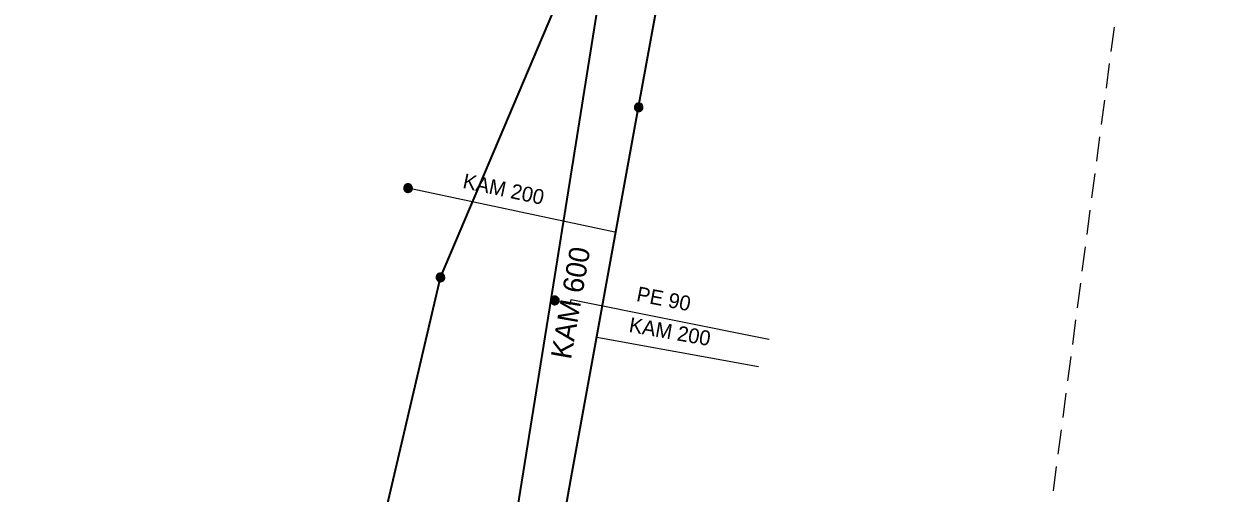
# Model space of a CAD drawing. Extents: x -867121 to -866743, y -1014362 to -1014088.
# Drawn here: x -866806.4 to -866742.8, y -1014182.3 to -1014157.2 of the extents above; entities that cross this region are included whole.
import ezdxf

# ---------------------------------------------------------------- set-up
doc = ezdxf.new("R2010")
doc.units = 0
doc.header["$LTSCALE"] = 0.44
doc.linetypes.add('MEDIUM_DASHED', pattern=[4.5, 3, -1.5])
for name, color, linetype, lineweight in [('1', 7, 'Continuous', 35), ('12', 7, 'Continuous', 13), ('21', 7, 'Continuous', 35), ('23', 7, 'Continuous', 25), ('3', 7, 'Continuous', 25), ('32', 7, 'Continuous', 13), ('62', 7, 'MEDIUM_DASHED', 25)]:
    doc.layers.add(name, color=color, linetype=linetype, lineweight=lineweight)

msp = doc.modelspace()

# ---------------------------------------------------------------- linework, layer by layer
at = {"layer": '1'}
msp.add_lwpolyline([(-866791.979, -1014256.58), (-866792.57, -1014256.02), (-866792.709, -1014255.69), (-866792.69, -1014255.37), (-866792.5, -1014254.9), (-866792.3, -1014254.24), (-866792, -1014252.89), (-866783.03, -1014202.67), (-866778.1, -1014171.95), (-866772.02, -1014133.72), (-866768.851, -1014115.7)], dxfattribs=at)
at = {"layer": '12'}
for points in [[(-866777.676, -1014172.009), (-866777.682, -1014171.957), (-866777.699, -1014171.907), (-866777.728, -1014171.863), (-866777.765, -1014171.826), (-866777.81, -1014171.799), (-866777.86, -1014171.782), (-866777.913, -1014171.778), (-866777.965, -1014171.785), (-866778.014, -1014171.804), (-866778.057, -1014171.833), (-866778.093, -1014171.872), (-866778.119, -1014171.917), (-866778.135, -1014171.968), (-866778.138, -1014172.02), (-866778.13, -1014172.072), (-866778.11, -1014172.121), (-866778.079, -1014172.164), (-866778.04, -1014172.198), (-866777.994, -1014172.224), (-866777.943, -1014172.238), (-866777.89, -1014172.24), (-866777.839, -1014172.23), (-866777.791, -1014172.209), (-866777.748, -1014172.178), (-866777.714, -1014172.137), (-866777.69, -1014172.091), (-866777.678, -1014172.04)], [(-866777.706, -1014172.009), (-866777.712, -1014171.96), (-866777.729, -1014171.914), (-866777.757, -1014171.874), (-866777.794, -1014171.842), (-866777.838, -1014171.82), (-866777.886, -1014171.809), (-866777.935, -1014171.809), (-866777.982, -1014171.822), (-866778.025, -1014171.846), (-866778.061, -1014171.879), (-866778.088, -1014171.92), (-866778.104, -1014171.967), (-866778.108, -1014172.016), (-866778.101, -1014172.064), (-866778.082, -1014172.109), (-866778.052, -1014172.149), (-866778.014, -1014172.18), (-866777.97, -1014172.2), (-866777.922, -1014172.21), (-866777.873, -1014172.208), (-866777.826, -1014172.193), (-866777.783, -1014172.168), (-866777.749, -1014172.134), (-866777.723, -1014172.092), (-866777.709, -1014172.045)], [(-866777.736, -1014172.009), (-866777.742, -1014171.964), (-866777.759, -1014171.922), (-866777.787, -1014171.887), (-866777.823, -1014171.86), (-866777.865, -1014171.843), (-866777.91, -1014171.838), (-866777.955, -1014171.844), (-866777.996, -1014171.863), (-866778.031, -1014171.891), (-866778.058, -1014171.928), (-866778.074, -1014171.97), (-866778.078, -1014172.015), (-866778.071, -1014172.06), (-866778.052, -1014172.101), (-866778.023, -1014172.135), (-866777.986, -1014172.161), (-866777.943, -1014172.177), (-866777.898, -1014172.18), (-866777.853, -1014172.172), (-866777.813, -1014172.152), (-866777.779, -1014172.123), (-866777.753, -1014172.085), (-866777.739, -1014172.042)], [(-866777.766, -1014172.009), (-866777.771, -1014171.968), (-866777.789, -1014171.931), (-866777.816, -1014171.9), (-866777.851, -1014171.879), (-866777.891, -1014171.868), (-866777.932, -1014171.87), (-866777.971, -1014171.883), (-866778.005, -1014171.907), (-866778.03, -1014171.939), (-866778.045, -1014171.977), (-866778.048, -1014172.018), (-866778.04, -1014172.058), (-866778.02, -1014172.094), (-866777.991, -1014172.123), (-866777.954, -1014172.142), (-866777.914, -1014172.15), (-866777.873, -1014172.146), (-866777.835, -1014172.131), (-866777.803, -1014172.105), (-866777.78, -1014172.071), (-866777.767, -1014172.032)], [(-866777.796, -1014172.009), (-866777.801, -1014171.973), (-866777.819, -1014171.941), (-866777.845, -1014171.916), (-866777.879, -1014171.901), (-866777.915, -1014171.898), (-866777.95, -1014171.906), (-866777.981, -1014171.926), (-866778.004, -1014171.954), (-866778.017, -1014171.988), (-866778.017, -1014172.025), (-866778.006, -1014172.06), (-866777.985, -1014172.089), (-866777.955, -1014172.11), (-866777.92, -1014172.12), (-866777.883, -1014172.118), (-866777.849, -1014172.104), (-866777.822, -1014172.081), (-866777.803, -1014172.049), (-866777.796, -1014172.014)], [(-866777.826, -1014172.009), (-866777.831, -1014171.978), (-866777.848, -1014171.952), (-866777.874, -1014171.935), (-866777.904, -1014171.928), (-866777.935, -1014171.932), (-866777.962, -1014171.949), (-866777.98, -1014171.973), (-866777.988, -1014172.004), (-866777.984, -1014172.034), (-866777.969, -1014172.062), (-866777.945, -1014172.081), (-866777.915, -1014172.09), (-866777.884, -1014172.087), (-866777.856, -1014172.073), (-866777.836, -1014172.049), (-866777.826, -1014172.02)], [(-866777.856, -1014172.009), (-866777.861, -1014171.985), (-866777.878, -1014171.967), (-866777.901, -1014171.958), (-866777.925, -1014171.961), (-866777.946, -1014171.975), (-866777.957, -1014171.997), (-866777.957, -1014172.022), (-866777.945, -1014172.043), (-866777.925, -1014172.057), (-866777.9, -1014172.06), (-866777.877, -1014172.051), (-866777.861, -1014172.033)], [(-866777.886, -1014172.009), (-866777.891, -1014171.994), (-866777.906, -1014171.988), (-866777.921, -1014171.992), (-866777.928, -1014172.006), (-866777.924, -1014172.021), (-866777.911, -1014172.03), (-866777.896, -1014172.027), (-866777.886, -1014172.015)]]:
    msp.add_lwpolyline(points, close=True, dxfattribs=at)
at = {"layer": '21'}
msp.add_line((-866773.421, -1014161.649), (-866768.346, -1014133.738), dxfattribs=at)
for points in [[(-866867.906, -1014313.414), (-866804.195, -1014269.207), (-866794.318, -1014228.125), (-866791.378, -1014202.173), (-866784.04, -1014170.77), (-866768.345, -1014133.735)], [(-866783.712, -1014219.159), (-866777.049, -1014181.604), (-866773.421, -1014161.649)]]:
    msp.add_lwpolyline(points, dxfattribs=at)
at = {"layer": '23'}
for p, q in [((-866785.86, -1014165.95), (-866774.697, -1014168.332)), ((-866767.003, -1014175.567), (-866775.665, -1014173.992))]:
    msp.add_line(p, q, dxfattribs=at)
at = {"layer": '3'}
msp.add_lwpolyline([(-866778.1, -1014171.95), (-866777.9, -1014172), (-866777.07, -1014172.21), (-866777.03, -1014171.95), (-866766.45, -1014174.08), (-866766.429, -1014174.084)], dxfattribs=at)
at = {"layer": '32'}
for points in [[(-866773.19, -1014161.649), (-866773.196, -1014161.597), (-866773.213, -1014161.547), (-866773.242, -1014161.503), (-866773.279, -1014161.466), (-866773.324, -1014161.439), (-866773.374, -1014161.422), (-866773.427, -1014161.418), (-866773.478, -1014161.425), (-866773.527, -1014161.444), (-866773.571, -1014161.473), (-866773.607, -1014161.512), (-866773.633, -1014161.557), (-866773.649, -1014161.608), (-866773.652, -1014161.66), (-866773.644, -1014161.712), (-866773.624, -1014161.761), (-866773.593, -1014161.804), (-866773.554, -1014161.838), (-866773.508, -1014161.864), (-866773.456, -1014161.878), (-866773.404, -1014161.88), (-866773.353, -1014161.87), (-866773.304, -1014161.849), (-866773.262, -1014161.818), (-866773.228, -1014161.777), (-866773.204, -1014161.731), (-866773.191, -1014161.68)], [(-866773.22, -1014161.649), (-866773.226, -1014161.6), (-866773.243, -1014161.554), (-866773.271, -1014161.514), (-866773.308, -1014161.482), (-866773.352, -1014161.46), (-866773.4, -1014161.449), (-866773.449, -1014161.449), (-866773.495, -1014161.462), (-866773.539, -1014161.486), (-866773.575, -1014161.519), (-866773.602, -1014161.56), (-866773.618, -1014161.607), (-866773.622, -1014161.656), (-866773.615, -1014161.704), (-866773.596, -1014161.749), (-866773.566, -1014161.789), (-866773.527, -1014161.82), (-866773.483, -1014161.84), (-866773.436, -1014161.85), (-866773.387, -1014161.848), (-866773.34, -1014161.833), (-866773.297, -1014161.808), (-866773.262, -1014161.774), (-866773.237, -1014161.732), (-866773.223, -1014161.685)], [(-866773.25, -1014161.649), (-866773.255, -1014161.604), (-866773.272, -1014161.562), (-866773.301, -1014161.527), (-866773.337, -1014161.5), (-866773.379, -1014161.483), (-866773.424, -1014161.478), (-866773.468, -1014161.484), (-866773.51, -1014161.503), (-866773.544, -1014161.531), (-866773.571, -1014161.568), (-866773.588, -1014161.61), (-866773.592, -1014161.655), (-866773.585, -1014161.7), (-866773.566, -1014161.741), (-866773.537, -1014161.775), (-866773.5, -1014161.801), (-866773.456, -1014161.817), (-866773.412, -1014161.82), (-866773.367, -1014161.812), (-866773.326, -1014161.792), (-866773.293, -1014161.763), (-866773.267, -1014161.725), (-866773.253, -1014161.682)], [(-866773.28, -1014161.649), (-866773.284, -1014161.608), (-866773.303, -1014161.571), (-866773.33, -1014161.54), (-866773.365, -1014161.519), (-866773.405, -1014161.508), (-866773.446, -1014161.51), (-866773.485, -1014161.523), (-866773.519, -1014161.547), (-866773.544, -1014161.579), (-866773.559, -1014161.617), (-866773.561, -1014161.658), (-866773.554, -1014161.698), (-866773.534, -1014161.734), (-866773.505, -1014161.763), (-866773.468, -1014161.782), (-866773.428, -1014161.79), (-866773.387, -1014161.786), (-866773.348, -1014161.771), (-866773.316, -1014161.745), (-866773.294, -1014161.711), (-866773.281, -1014161.672)], [(-866773.309, -1014161.649), (-866773.315, -1014161.613), (-866773.333, -1014161.581), (-866773.358, -1014161.556), (-866773.392, -1014161.541), (-866773.429, -1014161.538), (-866773.463, -1014161.546), (-866773.495, -1014161.566), (-866773.517, -1014161.594), (-866773.531, -1014161.628), (-866773.531, -1014161.665), (-866773.52, -1014161.7), (-866773.499, -1014161.729), (-866773.468, -1014161.75), (-866773.434, -1014161.76), (-866773.397, -1014161.758), (-866773.363, -1014161.744), (-866773.336, -1014161.721), (-866773.316, -1014161.689), (-866773.309, -1014161.654)], [(-866773.34, -1014161.649), (-866773.345, -1014161.618), (-866773.362, -1014161.592), (-866773.387, -1014161.575), (-866773.418, -1014161.568), (-866773.449, -1014161.572), (-866773.476, -1014161.589), (-866773.494, -1014161.613), (-866773.502, -1014161.644), (-866773.498, -1014161.674), (-866773.483, -1014161.702), (-866773.458, -1014161.721), (-866773.429, -1014161.73), (-866773.397, -1014161.727), (-866773.37, -1014161.713), (-866773.35, -1014161.689), (-866773.34, -1014161.66)], [(-866773.37, -1014161.649), (-866773.375, -1014161.625), (-866773.392, -1014161.607), (-866773.414, -1014161.598), (-866773.439, -1014161.601), (-866773.46, -1014161.615), (-866773.471, -1014161.637), (-866773.471, -1014161.662), (-866773.458, -1014161.683), (-866773.439, -1014161.697), (-866773.414, -1014161.7), (-866773.391, -1014161.691), (-866773.375, -1014161.673)], [(-866773.4, -1014161.649), (-866773.405, -1014161.634), (-866773.419, -1014161.628), (-866773.434, -1014161.632), (-866773.441, -1014161.646), (-866773.438, -1014161.661), (-866773.424, -1014161.67), (-866773.409, -1014161.667), (-866773.4, -1014161.655)], [(-866785.542, -1014165.983), (-866785.548, -1014165.931), (-866785.565, -1014165.881), (-866785.594, -1014165.837), (-866785.631, -1014165.8), (-866785.676, -1014165.773), (-866785.726, -1014165.756), (-866785.779, -1014165.752), (-866785.831, -1014165.759), (-866785.88, -1014165.778), (-866785.923, -1014165.807), (-866785.959, -1014165.846), (-866785.985, -1014165.891), (-866786.001, -1014165.942), (-866786.004, -1014165.994), (-866785.996, -1014166.046), (-866785.976, -1014166.095), (-866785.945, -1014166.138), (-866785.906, -1014166.172), (-866785.86, -1014166.198), (-866785.809, -1014166.212), (-866785.756, -1014166.214), (-866785.705, -1014166.204), (-866785.657, -1014166.183), (-866785.614, -1014166.152), (-866785.58, -1014166.111), (-866785.556, -1014166.065), (-866785.544, -1014166.014)], [(-866785.572, -1014165.983), (-866785.578, -1014165.934), (-866785.595, -1014165.888), (-866785.623, -1014165.848), (-866785.66, -1014165.816), (-866785.704, -1014165.794), (-866785.752, -1014165.783), (-866785.801, -1014165.783), (-866785.848, -1014165.796), (-866785.891, -1014165.82), (-866785.927, -1014165.853), (-866785.954, -1014165.894), (-866785.97, -1014165.941), (-866785.974, -1014165.99), (-866785.967, -1014166.038), (-866785.948, -1014166.083), (-866785.918, -1014166.123), (-866785.88, -1014166.154), (-866785.836, -1014166.174), (-866785.788, -1014166.184), (-866785.739, -1014166.182), (-866785.692, -1014166.167), (-866785.649, -1014166.142), (-866785.615, -1014166.108), (-866785.589, -1014166.066), (-866785.575, -1014166.019)], [(-866785.602, -1014165.983), (-866785.608, -1014165.938), (-866785.625, -1014165.896), (-866785.653, -1014165.861), (-866785.689, -1014165.834), (-866785.731, -1014165.817), (-866785.776, -1014165.812), (-866785.821, -1014165.818), (-866785.862, -1014165.837), (-866785.897, -1014165.865), (-866785.924, -1014165.902), (-866785.94, -1014165.944), (-866785.944, -1014165.989), (-866785.937, -1014166.034), (-866785.918, -1014166.075), (-866785.889, -1014166.109), (-866785.852, -1014166.135), (-866785.809, -1014166.151), (-866785.764, -1014166.154), (-866785.719, -1014166.146), (-866785.679, -1014166.126), (-866785.645, -1014166.097), (-866785.619, -1014166.059), (-866785.605, -1014166.016)], [(-866785.632, -1014165.983), (-866785.637, -1014165.942), (-866785.655, -1014165.905), (-866785.682, -1014165.874), (-866785.717, -1014165.853), (-866785.757, -1014165.842), (-866785.798, -1014165.844), (-866785.837, -1014165.857), (-866785.871, -1014165.881), (-866785.896, -1014165.913), (-866785.911, -1014165.951), (-866785.914, -1014165.992), (-866785.906, -1014166.032), (-866785.886, -1014166.068), (-866785.857, -1014166.097), (-866785.82, -1014166.116), (-866785.78, -1014166.124), (-866785.739, -1014166.12), (-866785.701, -1014166.105), (-866785.669, -1014166.079), (-866785.646, -1014166.045), (-866785.633, -1014166.006)], [(-866785.662, -1014165.983), (-866785.667, -1014165.947), (-866785.685, -1014165.915), (-866785.711, -1014165.89), (-866785.745, -1014165.875), (-866785.781, -1014165.872), (-866785.816, -1014165.88), (-866785.847, -1014165.9), (-866785.87, -1014165.928), (-866785.883, -1014165.962), (-866785.883, -1014165.999), (-866785.872, -1014166.034), (-866785.851, -1014166.063), (-866785.821, -1014166.084), (-866785.786, -1014166.094), (-866785.749, -1014166.092), (-866785.715, -1014166.078), (-866785.688, -1014166.055), (-866785.669, -1014166.023), (-866785.662, -1014165.988)], [(-866785.692, -1014165.983), (-866785.697, -1014165.952), (-866785.714, -1014165.926), (-866785.74, -1014165.909), (-866785.77, -1014165.902), (-866785.801, -1014165.906), (-866785.828, -1014165.923), (-866785.846, -1014165.947), (-866785.854, -1014165.978), (-866785.85, -1014166.008), (-866785.835, -1014166.036), (-866785.811, -1014166.055), (-866785.781, -1014166.064), (-866785.75, -1014166.061), (-866785.722, -1014166.047), (-866785.702, -1014166.023), (-866785.692, -1014165.994)], [(-866785.722, -1014165.983), (-866785.727, -1014165.959), (-866785.744, -1014165.941), (-866785.767, -1014165.932), (-866785.791, -1014165.935), (-866785.812, -1014165.949), (-866785.823, -1014165.971), (-866785.823, -1014165.996), (-866785.811, -1014166.017), (-866785.791, -1014166.031), (-866785.766, -1014166.034), (-866785.743, -1014166.025), (-866785.727, -1014166.007)], [(-866785.752, -1014165.983), (-866785.757, -1014165.968), (-866785.772, -1014165.962), (-866785.787, -1014165.966), (-866785.794, -1014165.98), (-866785.79, -1014165.995), (-866785.777, -1014166.004), (-866785.762, -1014166.001), (-866785.752, -1014165.989)], [(-866783.809, -1014170.77), (-866783.815, -1014170.718), (-866783.832, -1014170.668), (-866783.861, -1014170.624), (-866783.898, -1014170.587), (-866783.943, -1014170.56), (-866783.993, -1014170.543), (-866784.046, -1014170.539), (-866784.098, -1014170.546), (-866784.147, -1014170.565), (-866784.19, -1014170.594), (-866784.226, -1014170.633), (-866784.252, -1014170.678), (-866784.268, -1014170.729), (-866784.271, -1014170.781), (-866784.263, -1014170.833), (-866784.243, -1014170.882), (-866784.212, -1014170.925), (-866784.173, -1014170.959), (-866784.127, -1014170.985), (-866784.076, -1014170.999), (-866784.023, -1014171.001), (-866783.972, -1014170.991), (-866783.924, -1014170.97), (-866783.881, -1014170.939), (-866783.847, -1014170.898), (-866783.823, -1014170.852), (-866783.811, -1014170.801)], [(-866783.839, -1014170.77), (-866783.845, -1014170.721), (-866783.862, -1014170.675), (-866783.89, -1014170.635), (-866783.927, -1014170.603), (-866783.971, -1014170.581), (-866784.019, -1014170.57), (-866784.068, -1014170.57), (-866784.115, -1014170.583), (-866784.158, -1014170.607), (-866784.194, -1014170.64), (-866784.221, -1014170.681), (-866784.237, -1014170.728), (-866784.241, -1014170.777), (-866784.234, -1014170.825), (-866784.215, -1014170.87), (-866784.185, -1014170.91), (-866784.147, -1014170.941), (-866784.103, -1014170.961), (-866784.055, -1014170.971), (-866784.006, -1014170.969), (-866783.959, -1014170.954), (-866783.916, -1014170.929), (-866783.882, -1014170.895), (-866783.856, -1014170.853), (-866783.842, -1014170.806)], [(-866783.869, -1014170.77), (-866783.875, -1014170.725), (-866783.892, -1014170.683), (-866783.92, -1014170.648), (-866783.956, -1014170.621), (-866783.998, -1014170.604), (-866784.043, -1014170.599), (-866784.088, -1014170.605), (-866784.129, -1014170.624), (-866784.164, -1014170.652), (-866784.191, -1014170.689), (-866784.207, -1014170.731), (-866784.211, -1014170.776), (-866784.204, -1014170.821), (-866784.185, -1014170.862), (-866784.156, -1014170.896), (-866784.119, -1014170.922), (-866784.076, -1014170.938), (-866784.031, -1014170.941), (-866783.986, -1014170.933), (-866783.946, -1014170.913), (-866783.912, -1014170.884), (-866783.886, -1014170.846), (-866783.872, -1014170.803)], [(-866783.899, -1014170.77), (-866783.904, -1014170.729), (-866783.922, -1014170.692), (-866783.949, -1014170.661), (-866783.984, -1014170.64), (-866784.024, -1014170.629), (-866784.065, -1014170.631), (-866784.104, -1014170.644), (-866784.138, -1014170.668), (-866784.163, -1014170.7), (-866784.178, -1014170.738), (-866784.181, -1014170.779), (-866784.173, -1014170.819), (-866784.153, -1014170.855), (-866784.124, -1014170.884), (-866784.087, -1014170.903), (-866784.047, -1014170.911), (-866784.006, -1014170.907), (-866783.968, -1014170.892), (-866783.936, -1014170.866), (-866783.913, -1014170.832), (-866783.9, -1014170.793)], [(-866783.929, -1014170.77), (-866783.934, -1014170.734), (-866783.952, -1014170.702), (-866783.978, -1014170.677), (-866784.012, -1014170.662), (-866784.048, -1014170.659), (-866784.083, -1014170.667), (-866784.114, -1014170.687), (-866784.137, -1014170.715), (-866784.15, -1014170.749), (-866784.15, -1014170.786), (-866784.139, -1014170.821), (-866784.118, -1014170.85), (-866784.088, -1014170.871), (-866784.053, -1014170.881), (-866784.016, -1014170.879), (-866783.982, -1014170.865), (-866783.955, -1014170.842), (-866783.936, -1014170.81), (-866783.929, -1014170.775)], [(-866783.959, -1014170.77), (-866783.964, -1014170.739), (-866783.981, -1014170.713), (-866784.007, -1014170.696), (-866784.037, -1014170.689), (-866784.068, -1014170.693), (-866784.095, -1014170.71), (-866784.113, -1014170.734), (-866784.121, -1014170.765), (-866784.117, -1014170.795), (-866784.102, -1014170.823), (-866784.078, -1014170.842), (-866784.048, -1014170.851), (-866784.017, -1014170.848), (-866783.989, -1014170.834), (-866783.969, -1014170.81), (-866783.959, -1014170.781)], [(-866783.989, -1014170.77), (-866783.994, -1014170.746), (-866784.011, -1014170.728), (-866784.034, -1014170.719), (-866784.058, -1014170.722), (-866784.079, -1014170.736), (-866784.09, -1014170.758), (-866784.09, -1014170.783), (-866784.078, -1014170.804), (-866784.058, -1014170.818), (-866784.033, -1014170.821), (-866784.01, -1014170.812), (-866783.994, -1014170.794)], [(-866784.019, -1014170.77), (-866784.024, -1014170.755), (-866784.039, -1014170.749), (-866784.054, -1014170.753), (-866784.061, -1014170.767), (-866784.057, -1014170.782), (-866784.044, -1014170.791), (-866784.029, -1014170.788), (-866784.019, -1014170.776)]]:
    msp.add_lwpolyline(points, close=True, dxfattribs=at)
at = {"layer": '62'}
msp.add_lwpolyline([(-867067.961, -1014088.34), (-866742.796, -1014118.083), (-866768.922, -1014317.041), (-866980.741, -1014362.46), (-867121.419, -1014295.739)], close=True, dxfattribs=at)

# ---------------------------------------------------------------- texts
at = {"layer": '1'}
for s, height, rotation, p in [('KAM 200 ', 0.8, 348, (-866782.891, -1014165.969)), ('KAM 600 ', 1.1, 80, (-866777.054, -1014175.208)), ('PE 90 ', 0.8, 349, (-866773.581, -1014172.031)), ('KAM 200 ', 0.8, 350, (-866773.981, -1014173.688))]:
    msp.add_text(s, height=height, rotation=rotation, dxfattribs=at).set_placement(p)

doc.saveas('drawing.dxf')
